// Mitsubishi GX Works2 project: PID 自整定   PLC: FX1S

PROGRAM MAIN
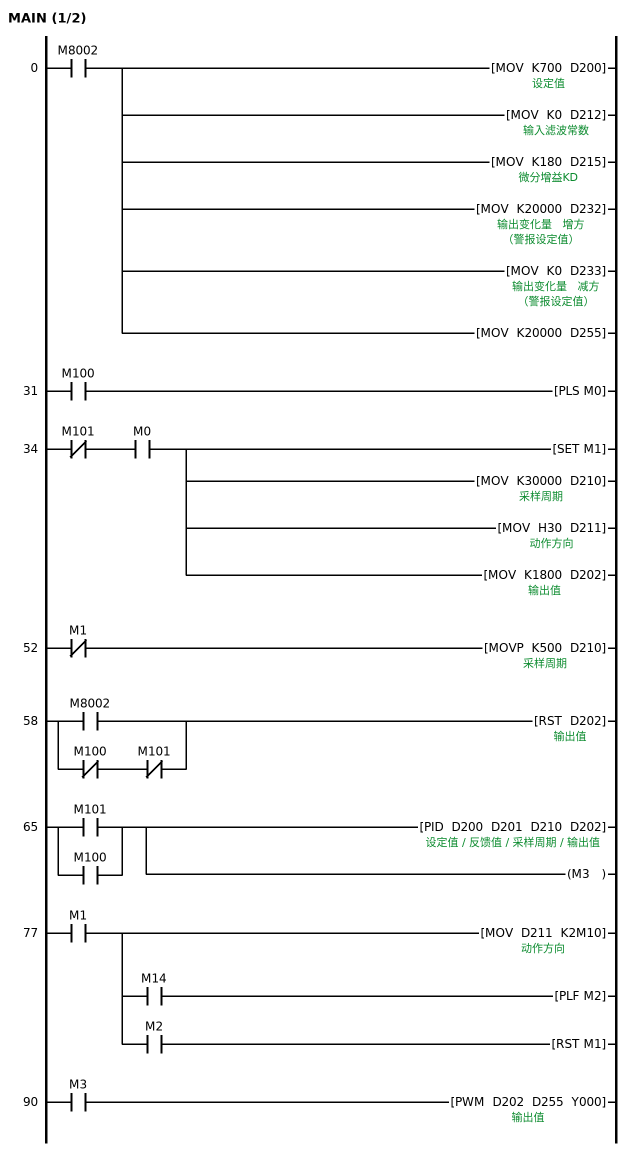
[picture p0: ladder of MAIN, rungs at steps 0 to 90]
0     LD      M8002
      MOV     K700 D200  ; 设定值
      MOV     K0 D212  ; 输入滤波常数
      MOV     K180 D215  ; 微分增益KD
      MOV     K20000 D232  ; 输出变化量   增方 （警报设定值）
      MOV     K0 D233  ; 输出变化量   减方 （警报设定值）
      MOV     K20000 D255
31    LD      M100
      PLS     M0
34    LDI     M101
      AND     M0
      SET     M1
      MOV     K30000 D210  ; 采样周期
      MOV     H30 D211  ; 动作方向
      MOV     K1800 D202  ; 输出值
52    LDI     M1
      MOVP    K500 D210
58    LD      M8002
      LDI     M100
      ANI     M101
      ORB
      RST     D202  ; 输出值
65    LD      M101
      OR      M100
      PID     D200 D201 D210 D202  ; 反馈值
      OUT     M3
77    LD      M1
      MOV     D211 K2M10
      MPS
      AND     M14
      PLF     M2
      MPP
      AND     M2
      RST     M1
90    LD      M3
      PWM     D202 D255 Y000
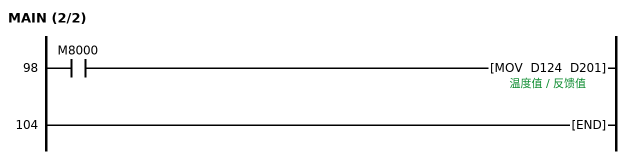
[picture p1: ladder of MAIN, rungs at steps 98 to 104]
98    LD      M8000
      MOV     D124 D201  ; 温度值
104   END
END_PROGRAM

// device comments not shown above
D213  ; 比例增益KP
D214  ; 积分时间T1
D216  ; 微分时间TD
D230  ; 输入变化量   增方 （警报设定值）
D231  ; 输入变化量   减方 （警报设定值）
D234  ; 警报输出
D235  ; 输出值
